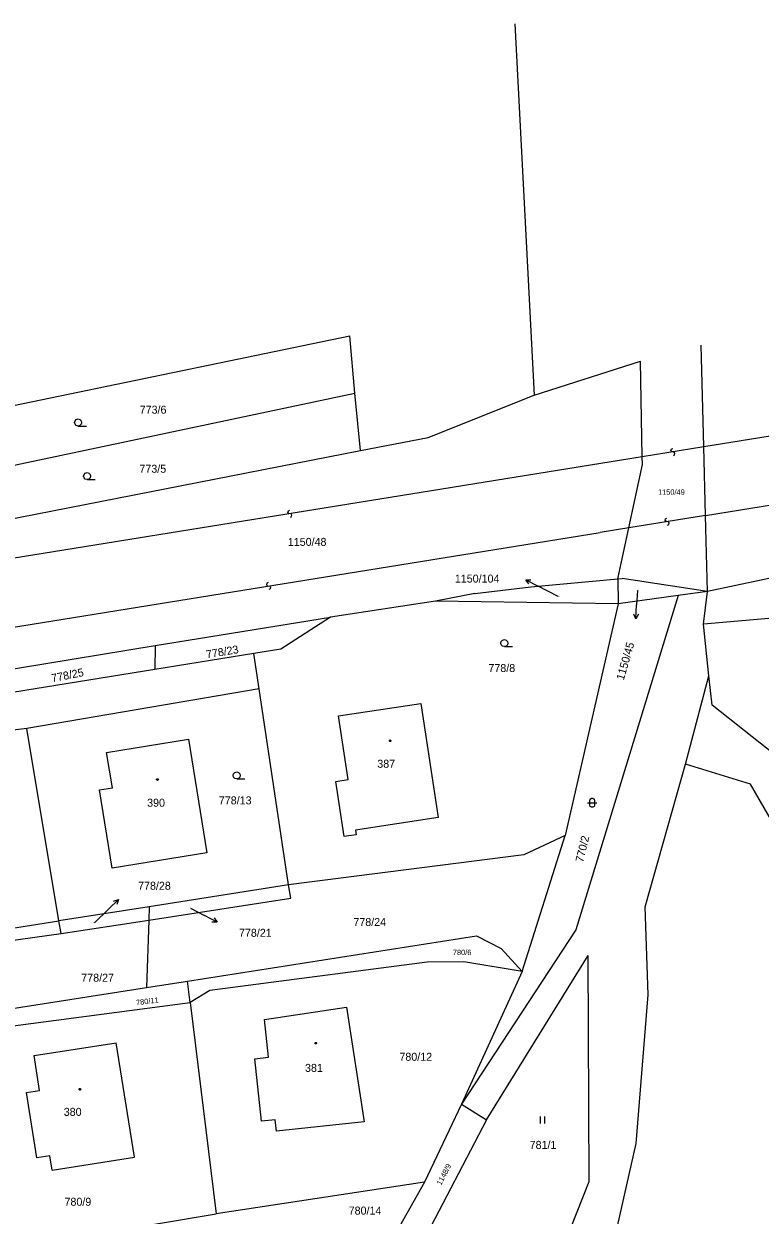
# Model space of a CAD drawing. Extents: x -747792 to -745414, y -1093712 to -1091463.
# Drawn here: x -745959.5 to -745881.2, y -1091645.8 to -1091519.2 of the extents above; entities that cross this region are included whole.
import ezdxf

# ---------------------------------------------------------------- set-up
doc = ezdxf.new("R2010")
doc.units = 0
for name, color, linetype in [('Pracovní_bod JDTM STC_VC', 7, 'Continuous'), ('Pracovní_bod JDTM STC_VC - výška', 7, 'Continuous'), ('Pracovní_bod JDTM STC_VC - číslo', 7, 'Continuous'), ('Pracovní_bod NN - výška', 7, 'Continuous'), ('Pracovní_bod polohopisu', 7, 'Continuous'), ('Pracovní_bod polohopisu - výška', 7, 'Continuous')]:
    doc.layers.add(name, color=color, linetype=linetype)

msp = doc.modelspace()

# ---------------------------------------------------------------- linework, layer by layer
at = {"layer": 'Pracovní_bod JDTM STC_VC - výška'}
for points in [[(-745920.56, -1091595.29), (-745920.51, -1091595.3), (-745920.49, -1091595.34), (-745920.48, -1091595.37), (-745920.49, -1091595.42), (-745920.53, -1091595.45), (-745920.56, -1091595.46), (-745920.6, -1091595.44), (-745920.64, -1091595.41), (-745920.65, -1091595.37), (-745920.64, -1091595.33), (-745920.59, -1091595.29)], [(-745945.3, -1091599.42), (-745945.25, -1091599.43), (-745945.23, -1091599.47), (-745945.22, -1091599.5), (-745945.23, -1091599.54), (-745945.27, -1091599.58), (-745945.3, -1091599.58), (-745945.34, -1091599.57), (-745945.38, -1091599.54), (-745945.39, -1091599.5), (-745945.38, -1091599.46), (-745945.33, -1091599.42)], [(-745928.47, -1091627.41), (-745928.42, -1091627.42), (-745928.4, -1091627.46), (-745928.39, -1091627.49), (-745928.4, -1091627.54), (-745928.44, -1091627.57), (-745928.47, -1091627.57), (-745928.51, -1091627.56), (-745928.54, -1091627.53), (-745928.55, -1091627.49), (-745928.54, -1091627.44), (-745928.5, -1091627.41)], [(-745953.53, -1091632.31), (-745953.48, -1091632.32), (-745953.46, -1091632.37), (-745953.45, -1091632.4), (-745953.46, -1091632.44), (-745953.5, -1091632.48), (-745953.53, -1091632.48), (-745953.58, -1091632.47), (-745953.6, -1091632.44), (-745953.61, -1091632.4), (-745953.6, -1091632.35), (-745953.57, -1091632.32)]]:
    msp.add_lwpolyline(points, close=True, dxfattribs=at)
at = {"layer": 'Pracovní_bod JDTM STC_VC - číslo'}
for points in [[(-745953.73, -1091561.94), (-745953.92, -1091561.89), (-745954.05, -1091561.75), (-745954.1, -1091561.56), (-745954.05, -1091561.38), (-745953.92, -1091561.24), (-745953.73, -1091561.19), (-745953.54, -1091561.24), (-745953.41, -1091561.38), (-745953.35, -1091561.56), (-745953.41, -1091561.75), (-745953.54, -1091561.89), (-745953.73, -1091561.94), (-745952.85, -1091561.94)], [(-745952.77, -1091567.63), (-745952.96, -1091567.58), (-745953.09, -1091567.44), (-745953.15, -1091567.26), (-745953.09, -1091567.07), (-745952.96, -1091566.93), (-745952.77, -1091566.88), (-745952.58, -1091566.93), (-745952.45, -1091567.07), (-745952.4, -1091567.26), (-745952.45, -1091567.44), (-745952.58, -1091567.58), (-745952.77, -1091567.63), (-745951.9, -1091567.63)], [(-745908.42, -1091585.37), (-745908.61, -1091585.32), (-745908.75, -1091585.18), (-745908.8, -1091585), (-745908.75, -1091584.81), (-745908.61, -1091584.67), (-745908.42, -1091584.62), (-745908.23, -1091584.67), (-745908.09, -1091584.81), (-745908.05, -1091585), (-745908.09, -1091585.18), (-745908.23, -1091585.32), (-745908.42, -1091585.37), (-745907.55, -1091585.37)], [(-745936.87, -1091599.43), (-745937.06, -1091599.38), (-745937.2, -1091599.24), (-745937.24, -1091599.05), (-745937.2, -1091598.87), (-745937.06, -1091598.73), (-745936.87, -1091598.68), (-745936.68, -1091598.73), (-745936.54, -1091598.87), (-745936.49, -1091599.05), (-745936.54, -1091599.24), (-745936.68, -1091599.38), (-745936.87, -1091599.43), (-745935.99, -1091599.43)], [(-745899.6, -1091601.96), (-745898.96, -1091601.96), (-745898.6, -1091601.96)], [(-745904.63, -1091635.28), (-745904.63, -1091636.03)], [(-745904.13, -1091636.03), (-745904.13, -1091635.28)]]:
    msp.add_lwpolyline(points, dxfattribs=at)
msp.add_lwpolyline([(-745899.35, -1091601.71), (-745899.3, -1091601.56), (-745899.18, -1091601.48), (-745899.02, -1091601.48), (-745898.9, -1091601.56), (-745898.84, -1091601.71), (-745898.84, -1091602.21), (-745898.9, -1091602.35), (-745899.02, -1091602.44), (-745899.18, -1091602.44), (-745899.3, -1091602.35), (-745899.35, -1091602.21)], close=True, dxfattribs=at)
at = {"layer": 'Pracovní_bod NN - výška'}
for points in [[(-745907.31, -1091519.21), (-745905.27, -1091558.66)], [(-745968.67, -1091561.42), (-745924.84, -1091552.35)], [(-745924.3, -1091558.46), (-745924.84, -1091552.35)], [(-745887.24, -1091564.16), (-745887.51, -1091553.35)], [(-745905.27, -1091558.66), (-745893.96, -1091555.05)], [(-745893.77, -1091565.21), (-745893.96, -1091555.05)], [(-745968.61, -1091567.78), (-745924.3, -1091558.46)], [(-745923.7, -1091564.54), (-745924.3, -1091558.46)], [(-745916.53, -1091563.14), (-745905.27, -1091558.66)], [(-745923.7, -1091564.54), (-745916.53, -1091563.14)], [(-745968.6, -1091573.31), (-745923.7, -1091564.54)], [(-745887.05, -1091571.43), (-745887.24, -1091564.16)], [(-745895.21, -1091572.75), (-745893.76, -1091566.01)], [(-745893.76, -1091566.01), (-745893.77, -1091565.21)], [(-745886.85, -1091579.51), (-745887.05, -1091571.43)], [(-745896.37, -1091578.17), (-745895.21, -1091572.75)], [(-745871.79, -1091576.32), (-745886.85, -1091579.51)], [(-745905.62, -1091579.03), (-745896.37, -1091578.17)], [(-745896.37, -1091578.17), (-745895.9, -1091578.12)], [(-745896.37, -1091578.17), (-745896.35, -1091580.83)], [(-745886.85, -1091579.51), (-745895.9, -1091578.12)], [(-745911.55, -1091579.72), (-745915.73, -1091580.53)], [(-745911.55, -1091579.72), (-745905.62, -1091579.03)], [(-745889.97, -1091579.94), (-745900.82, -1091615.45)], [(-745889.97, -1091579.94), (-745896.35, -1091580.83)], [(-745886.85, -1091579.51), (-745889.97, -1091579.94)], [(-745887.27, -1091582.98), (-745886.85, -1091579.51)], [(-745915.73, -1091580.53), (-745926.92, -1091582.23)], [(-745896.35, -1091580.83), (-745915.73, -1091580.53)], [(-745896.35, -1091580.83), (-745901.96, -1091605.44)], [(-745866.45, -1091581.17), (-745887.27, -1091582.98)], [(-745945.53, -1091585.26), (-745926.92, -1091582.23)], [(-745926.92, -1091582.23), (-745932.18, -1091585.64)], [(-745886.68, -1091588.47), (-745887.27, -1091582.98)], [(-745968.8, -1091589.06), (-745945.53, -1091585.26)], [(-745945.53, -1091585.26), (-745945.58, -1091587.8)], [(-745935.06, -1091586.1), (-745945.58, -1091587.8)], [(-745932.18, -1091585.64), (-745935.06, -1091586.1)], [(-745934.49, -1091589.87), (-745935.06, -1091586.1)], [(-745945.58, -1091587.8), (-745968.83, -1091591.55)], [(-745889.18, -1091597.85), (-745886.68, -1091588.47)], [(-745886.35, -1091591.58), (-745886.68, -1091588.47)], [(-745934.49, -1091589.87), (-745959.19, -1091594.06)], [(-745931.35, -1091610.67), (-745934.49, -1091589.87)], [(-745926.06, -1091592.73), (-745917.32, -1091591.42)], [(-745917.32, -1091591.42), (-745915.45, -1091603.54)], [(-745875.47, -1091600.18), (-745886.35, -1091591.58)], [(-745925.04, -1091599.49), (-745926.06, -1091592.73)], [(-745959.19, -1091594.06), (-745978.41, -1091596.41)], [(-745955.77, -1091614.51), (-745959.19, -1091594.06)], [(-745950.69, -1091596.61), (-745941.99, -1091595.19)], [(-745941.99, -1091595.19), (-745940.04, -1091607.28)], [(-745950.08, -1091600.38), (-745950.69, -1091596.61)], [(-745893.47, -1091613.02), (-745889.18, -1091597.85)], [(-745882.28, -1091599.98), (-745889.18, -1091597.85)], [(-745926.33, -1091599.69), (-745925.04, -1091599.49)], [(-745925.45, -1091605.56), (-745926.33, -1091599.69)], [(-745877.93, -1091607.53), (-745882.28, -1091599.98)], [(-745951.45, -1091600.6), (-745950.08, -1091600.38)], [(-745950.09, -1091608.91), (-745951.45, -1091600.6)], [(-745915.45, -1091603.54), (-745924.23, -1091604.86)], [(-745924.23, -1091604.86), (-745924.16, -1091605.36)], [(-745924.16, -1091605.36), (-745925.45, -1091605.56)], [(-745906.53, -1091619.88), (-745901.96, -1091605.44)], [(-745901.96, -1091605.44), (-745906.36, -1091607.5)], [(-745940.04, -1091607.28), (-745950.09, -1091608.91)], [(-745906.36, -1091607.5), (-745931.35, -1091610.67)], [(-745931.35, -1091610.67), (-745946.18, -1091613)], [(-745931.13, -1091612.11), (-745931.35, -1091610.67)], [(-745946.22, -1091614.42), (-745931.13, -1091612.11)], [(-745946.18, -1091613), (-745955.77, -1091614.51)], [(-745946.18, -1091613), (-745946.22, -1091614.42)], [(-745893.15, -1091622.38), (-745893.47, -1091613.02)], [(-745968.77, -1091616.55), (-745955.77, -1091614.51)], [(-745955.54, -1091615.85), (-745955.77, -1091614.51)], [(-745955.54, -1091615.85), (-745946.22, -1091614.42)], [(-745946.22, -1091614.42), (-745946.44, -1091621.58)], [(-745900.82, -1091615.45), (-745912.99, -1091633.97)], [(-745968.78, -1091617.68), (-745955.54, -1091615.85)], [(-745942.09, -1091620.9), (-745911.4, -1091616.09)], [(-745911.4, -1091616.09), (-745908.77, -1091617.45)], [(-745908.77, -1091617.45), (-745906.53, -1091619.88)], [(-745916.62, -1091618.88), (-745939.73, -1091621.92)], [(-745912.73, -1091618.86), (-745916.62, -1091618.88)], [(-745906.53, -1091619.88), (-745912.73, -1091618.86)], [(-745910.34, -1091635.63), (-745899.53, -1091618.19)], [(-745899.41, -1091642.18), (-745899.53, -1091618.19)], [(-745906.53, -1091619.88), (-745912.99, -1091633.97)], [(-745963.91, -1091624.31), (-745946.44, -1091621.58)], [(-745946.44, -1091621.58), (-745942.09, -1091620.9)], [(-745941.81, -1091623.17), (-745942.09, -1091620.9)], [(-745939.73, -1091621.92), (-745941.81, -1091623.17)], [(-745894.42, -1091638.17), (-745893.15, -1091622.38)], [(-745965.23, -1091626.27), (-745941.81, -1091623.17)], [(-745941.81, -1091623.17), (-745939.06, -1091645.64)], [(-745933.92, -1091625), (-745925.2, -1091623.66)], [(-745925.2, -1091623.66), (-745923.34, -1091635.84)], [(-745933.49, -1091628.99), (-745933.92, -1091625)], [(-745958.41, -1091628.82), (-745949.68, -1091627.46)], [(-745947.73, -1091639.62), (-745949.68, -1091627.46)], [(-745957.82, -1091632.52), (-745958.41, -1091628.82)], [(-745934.96, -1091629.15), (-745933.49, -1091628.99)], [(-745934.24, -1091635.8), (-745934.96, -1091629.15)], [(-745959.21, -1091632.74), (-745957.82, -1091632.52)], [(-745958.1, -1091639.68), (-745959.21, -1091632.74)], [(-745912.99, -1091633.97), (-745916.92, -1091642.28)], [(-745912.99, -1091633.97), (-745910.34, -1091635.63)], [(-745932.77, -1091635.64), (-745934.24, -1091635.8)], [(-745932.64, -1091636.85), (-745932.77, -1091635.64)], [(-745910.34, -1091635.63), (-745917.08, -1091648.59)], [(-745923.34, -1091635.84), (-745932.64, -1091636.85)], [(-745897.14, -1091650.23), (-745894.42, -1091638.17)], [(-745956.72, -1091639.46), (-745958.1, -1091639.68)], [(-745956.47, -1091641), (-745956.72, -1091639.46)], [(-745956.47, -1091641), (-745947.73, -1091639.62)], [(-745916.92, -1091642.28), (-745939.06, -1091645.64)], [(-745916.92, -1091642.28), (-745920.67, -1091648.93)], [(-745912.98, -1091676.47), (-745899.41, -1091642.18)], [(-745945.61, -1091646.72), (-745939.06, -1091645.64)]]:
    msp.add_lwpolyline(points, dxfattribs=at)
at = {"layer": 'Pracovní_bod polohopisu'}
for points in [[(-745823.53, -1091553.92), (-745887.24, -1091564.16)], [(-745887.05, -1091571.43), (-745821.34, -1091560.83)], [(-745887.24, -1091564.16), (-745893.77, -1091565.21)], [(-745890.47, -1091565.06), (-745890.33, -1091564.99), (-745890.3, -1091564.82), (-745890.39, -1091564.7), (-745890.64, -1091564.66), (-745890.72, -1091564.53), (-745890.67, -1091564.37), (-745890.54, -1091564.31)], [(-745893.77, -1091565.21), (-745968.65, -1091577.3)], [(-745931.17, -1091571.63), (-745931.03, -1091571.56), (-745931, -1091571.39), (-745931.09, -1091571.27), (-745931.34, -1091571.23), (-745931.42, -1091571.1), (-745931.38, -1091570.94), (-745931.25, -1091570.88)], [(-745887.05, -1091571.43), (-745895.21, -1091572.75)], [(-745891.09, -1091572.46), (-745890.95, -1091572.39), (-745890.92, -1091572.23), (-745891.01, -1091572.11), (-745891.26, -1091572.06), (-745891.34, -1091571.93), (-745891.3, -1091571.78), (-745891.17, -1091571.72)], [(-745968.74, -1091584.63), (-745898.24, -1091573.24)], [(-745895.21, -1091572.75), (-745898.24, -1091573.24)], [(-745933.53, -1091578.56), (-745933.67, -1091578.63), (-745933.7, -1091578.8), (-745933.61, -1091578.92), (-745933.36, -1091578.96), (-745933.28, -1091579.09), (-745933.32, -1091579.25), (-745933.45, -1091579.31)]]:
    msp.add_lwpolyline(points, dxfattribs=at)
at = {"layer": 'Pracovní_bod polohopisu - výška'}
for points in [[(-745906.16, -1091578.26), (-745904.83, -1091578.95)], [(-745905.83, -1091578.71), (-745906.16, -1091578.26), (-745905.6, -1091578.27)], [(-745902.7, -1091580.06), (-745904.83, -1091578.95)], [(-745894.27, -1091579.41), (-745894.37, -1091580.93)], [(-745894.47, -1091582.43), (-745894.37, -1091580.93)], [(-745894.18, -1091581.94), (-745894.47, -1091582.43), (-745894.68, -1091581.91)], [(-745949.43, -1091612.24), (-745950.51, -1091613.28)], [(-745949.96, -1091612.41), (-745949.43, -1091612.24), (-745949.62, -1091612.77)], [(-745951.99, -1091614.7), (-745950.51, -1091613.28)], [(-745941.77, -1091613.14), (-745940.28, -1091613.94)], [(-745938.96, -1091614.65), (-745940.28, -1091613.94)], [(-745939.28, -1091614.19), (-745938.96, -1091614.65), (-745939.52, -1091614.63)]]:
    msp.add_lwpolyline(points, dxfattribs=at)

# ---------------------------------------------------------------- texts
at = {"layer": 'Pracovní_bod JDTM STC_VC'}
for s, height, p in [('773/6', 0.85, (-745947.18, -1091560.63)), ('773/5', 0.85, (-745947.21, -1091566.9)), ('1150/49', 0.57, (-745892.1, -1091569.24)), ('1150/48', 0.85, (-745931.44, -1091574.67)), ('1150/104', 0.05, (-745902.83, -1091580.06)), ('1150/45', 0.05, (-745894.39, -1091579.41)), ('778/8', 0.85, (-745910.12, -1091588.07)), ('387', 0.85, (-745921.93, -1091598.24)), ('390', 0.85, (-745946.39, -1091602.38)), ('778/13', 0.85, (-745938.77, -1091602.13)), ('778/24', 0.85, (-745924.47, -1091615.05)), ('780/6', 0.57, (-745913.9, -1091618.14)), ('778/27', 0.85, (-745953.39, -1091620.97)), ('780/12', 0.85, (-745919.58, -1091629.37)), ('381', 0.85, (-745929.61, -1091630.55)), ('380', 0.85, (-745955.25, -1091635.22)), ('781/1', 0.85, (-745905.74, -1091638.73)), ('780/9', 0.85, (-745955.17, -1091644.77))]:
    msp.add_text(s, height=height, dxfattribs=at).set_placement(p)
for s, height, rotation, p in [('778/23', 0.85, 9.5111, (-745940.05, -1091586.63)), ('778/25', 0.85, 11.1154, (-745956.48, -1091589.16)), ('770/2', 0.85, 76.3753, (-745900.06, -1091608.34)), ('778/21', 0.05, 9.8549, (-745941.88, -1091613.16)), ('778/28', 0.05, 10.0841, (-745952.11, -1091614.72)), ('780/11', 0.57, 7.3912, (-745947.53, -1091623.48)), ('1148/9', 0.57, 62.6816, (-745915.15, -1091642.64))]:
    msp.add_text(s, height=height, rotation=rotation, dxfattribs=at).set_placement(p)
at = {"layer": 'Pracovní_bod polohopisu - výška'}
for s, p in [('1150/104', (-745913.69, -1091578.57)), ('778/28', (-745947.35, -1091611.2)), ('778/21', (-745936.63, -1091616.2)), ('780/14', (-745924.97, -1091645.71))]:
    msp.add_text(s, height=0.85, dxfattribs=at).set_placement(p)
msp.add_text('1150/45', height=0.85, rotation=73.9116, dxfattribs=at).set_placement((-745895.74, -1091589))

doc.saveas('drawing.dxf')
